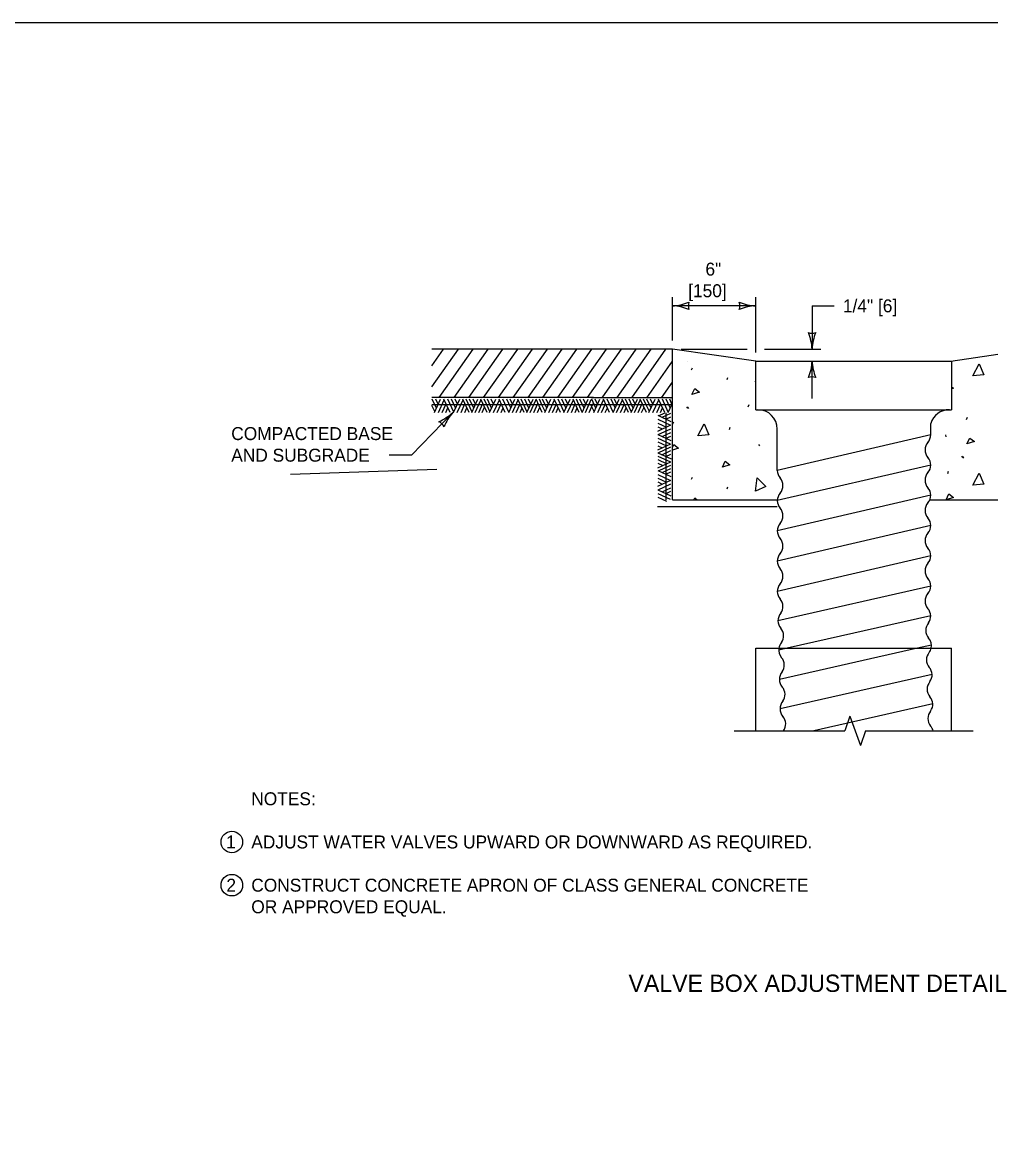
# Model space of a CAD drawing. Extents: x 49991.4 to 50021, y 49987.6 to 50011.4.
# Drawn here: x 50008.62 to 50013.11, y 49993.82 to 49999 of the extents above; entities that cross this region are included whole.
import ezdxf

# ---------------------------------------------------------------- set-up
doc = ezdxf.new("R2010")
doc.units = 0
for name, color, linetype in [('Level 1', 7, 'Continuous'), ('Level 2', 7, 'Continuous'), ('Level 3', 7, 'Continuous'), ('Level 4', 7, 'Continuous'), ('Level 6', 7, 'Continuous')]:
    doc.layers.add(name, color=color, linetype=linetype)

msp = doc.modelspace()

# ---------------------------------------------------------------- linework, layer by layer
at = {"layer": 'Level 1'}
for p, q in [((50011.6341, 49997.4869), (50010.5195, 49997.4869)), ((50010.5195, 49997.4096), (50010.5736, 49997.4869)), ((50010.5195, 49997.3116), (50010.6423, 49997.4869)), ((50010.5534, 49997.2619), (50010.711, 49997.4869)), ((50010.6221, 49997.2619), (50010.7796, 49997.4869)), ((50010.6908, 49997.2619), (50010.8484, 49997.4869)), ((50010.7594, 49997.2619), (50010.917, 49997.4869)), ((50010.8281, 49997.2619), (50010.9857, 49997.4869)), ((50010.8968, 49997.2619), (50011.0543, 49997.4869)), ((50010.9654, 49997.2619), (50011.123, 49997.4869)), ((50011.0341, 49997.2619), (50011.1916, 49997.4869)), ((50011.1028, 49997.2619), (50011.2603, 49997.4869)), ((50011.1714, 49997.2619), (50011.329, 49997.4867)), ((50011.2402, 49997.2619), (50011.3975, 49997.4869)), ((50011.3086, 49997.2617), (50011.4663, 49997.4869)), ((50011.3775, 49997.2619), (50011.5351, 49997.487)), ((50011.4458, 49997.2615), (50011.6035, 49997.487)), ((50011.6341, 49997.4589), (50011.6341, 49997.4869)), ((50012.0195, 49997.4313), (50011.6341, 49997.4869)), ((50012.9239, 49997.4313), (50013.3039, 49997.4869)), ((50011.5146, 49997.2618), (50011.6336, 49997.4316)), ((50011.6341, 49996.7892), (50011.6341, 49997.4589)), ((50011.7013, 49997.4303), (50011.7019, 49997.4312)), ((50012.0195, 49997.4313), (50012.9263, 49997.4313)), ((50012.0195, 49997.2063), (50012.0195, 49997.4313)), ((50012.9263, 49997.4313), (50012.9263, 49997.2063)), ((50011.7219, 49997.3902), (50011.7262, 49997.4)), ((50011.3679, 49997.3458), (50011.3685, 49997.3473)), ((50011.5832, 49997.2616), (50011.6341, 49997.3343)), ((50011.8865, 49997.3458), (50011.8908, 49997.3556)), ((50011.2685, 49997.2619), (50010.5195, 49997.2619)), ((50010.5195, 49997.2304), (50011.2685, 49997.2304)), ((50010.533, 49997.1974), (50010.5195, 49997.2263)), ((50010.5406, 49997.2138), (50010.5214, 49997.2549)), ((50010.5313, 49997.1936), (50010.5597, 49997.2549)), ((50010.5488, 49997.2315), (50010.5382, 49997.2549)), ((50010.5496, 49997.1936), (50010.5768, 49997.2521)), ((50010.5671, 49997.1936), (50010.5856, 49997.2334)), ((50010.6041, 49997.1936), (50010.5755, 49997.2549)), ((50010.5845, 49997.1936), (50010.5942, 49997.2147)), ((50010.6208, 49997.1953), (50010.5932, 49997.2549)), ((50010.6296, 49997.2143), (50010.6109, 49997.2549)), ((50010.6201, 49997.1936), (50010.6485, 49997.2549)), ((50010.6376, 49997.2322), (50010.6273, 49997.2549)), ((50010.637, 49997.1936), (50010.6641, 49997.2519)), ((50010.6546, 49997.1936), (50010.6729, 49997.2334)), ((50010.6915, 49997.1936), (50010.6628, 49997.2549)), ((50010.6725, 49997.1936), (50010.6818, 49997.2141)), ((50010.7054, 49997.1955), (50010.6778, 49997.2549)), ((50010.7136, 49997.2132), (50010.6944, 49997.2549)), ((50010.7045, 49997.1936), (50010.7329, 49997.2551)), ((50010.7222, 49997.2317), (50010.7115, 49997.2549)), ((50010.7197, 49997.1936), (50010.7471, 49997.253)), ((50010.7365, 49997.1936), (50010.7555, 49997.2353)), ((50010.775, 49997.1936), (50010.7466, 49997.2549)), ((50010.7527, 49997.1936), (50010.7637, 49997.2178)), ((50010.775, 49997.2263), (50010.7618, 49997.2549)), ((50010.7885, 49997.1974), (50010.775, 49997.2263)), ((50010.7961, 49997.2138), (50010.7769, 49997.2549)), ((50010.7868, 49997.1936), (50010.8152, 49997.2549)), ((50010.8043, 49997.2315), (50010.7936, 49997.2549)), ((50010.8051, 49997.1936), (50010.8323, 49997.2521)), ((50010.8226, 49997.1936), (50010.8411, 49997.2334)), ((50010.8595, 49997.1936), (50010.831, 49997.2549)), ((50010.8399, 49997.1936), (50010.8496, 49997.2147)), ((50010.8763, 49997.1953), (50010.8487, 49997.2549)), ((50010.8851, 49997.2143), (50010.8664, 49997.2549)), ((50010.8755, 49997.1936), (50010.9039, 49997.2549)), ((50010.8931, 49997.2322), (50010.8828, 49997.2549)), ((50010.8925, 49997.1936), (50010.9196, 49997.2519)), ((50010.91, 49997.1936), (50010.9283, 49997.2334)), ((50010.947, 49997.1936), (50010.9182, 49997.2549)), ((50010.9279, 49997.1936), (50010.9373, 49997.2141)), ((50010.9609, 49997.1955), (50010.9333, 49997.2549)), ((50010.9691, 49997.2132), (50010.9498, 49997.2549)), ((50010.9599, 49997.1936), (50010.9883, 49997.2551)), ((50010.9777, 49997.2317), (50010.967, 49997.2549)), ((50010.9752, 49997.1936), (50011.0026, 49997.253)), ((50010.9919, 49997.1936), (50011.011, 49997.2353)), ((50011.0304, 49997.1936), (50011.002, 49997.2549)), ((50011.0081, 49997.1936), (50011.0192, 49997.2178)), ((50011.0304, 49997.2263), (50011.0173, 49997.2549)), ((50011.0439, 49997.1974), (50011.0304, 49997.2263)), ((50011.0516, 49997.2138), (50011.0323, 49997.2549)), ((50011.0422, 49997.1936), (50011.0706, 49997.2549)), ((50011.0598, 49997.2315), (50011.0491, 49997.2549)), ((50011.0605, 49997.1936), (50011.0878, 49997.2521)), ((50011.078, 49997.1936), (50011.0965, 49997.2334)), ((50011.115, 49997.1936), (50011.0864, 49997.2549)), ((50011.0954, 49997.1936), (50011.1051, 49997.2147)), ((50011.1318, 49997.1953), (50011.1041, 49997.2549)), ((50011.1405, 49997.2143), (50011.1219, 49997.2549)), ((50011.131, 49997.1936), (50011.1594, 49997.2549)), ((50011.1485, 49997.2322), (50011.1382, 49997.2549)), ((50011.148, 49997.1936), (50011.175, 49997.2519)), ((50011.1655, 49997.1936), (50011.1838, 49997.2334)), ((50011.2024, 49997.1936), (50011.1737, 49997.2549)), ((50011.1834, 49997.1936), (50011.1927, 49997.2141)), ((50011.2163, 49997.1955), (50011.1887, 49997.2549)), ((50011.2245, 49997.2132), (50011.2053, 49997.2549)), ((50011.2154, 49997.1936), (50011.2438, 49997.2551)), ((50011.2331, 49997.2317), (50011.2224, 49997.2549)), ((50011.2306, 49997.1936), (50011.2581, 49997.253)), ((50011.2474, 49997.1936), (50011.2664, 49997.2353)), ((50011.2579, 49997.2619), (50011.6341, 49997.2619)), ((50011.2579, 49997.2304), (50011.6341, 49997.2304)), ((50011.2714, 49997.1974), (50011.2579, 49997.2263)), ((50011.279, 49997.2138), (50011.2598, 49997.2549)), ((50011.2697, 49997.1936), (50011.2981, 49997.2549)), ((50011.2872, 49997.2315), (50011.2766, 49997.2549)), ((50011.288, 49997.1936), (50011.3152, 49997.2521)), ((50011.3055, 49997.1936), (50011.324, 49997.2334)), ((50011.3425, 49997.1936), (50011.3139, 49997.2549)), ((50011.3229, 49997.1936), (50011.3326, 49997.2147)), ((50011.3592, 49997.1953), (50011.3316, 49997.2549)), ((50011.368, 49997.2143), (50011.3493, 49997.2549)), ((50011.3585, 49997.1936), (50011.3869, 49997.2549)), ((50011.376, 49997.2322), (50011.3657, 49997.2549)), ((50011.3754, 49997.1936), (50011.4025, 49997.2519)), ((50011.393, 49997.1936), (50011.4112, 49997.2334)), ((50011.4299, 49997.1936), (50011.4011, 49997.2549)), ((50011.4109, 49997.1936), (50011.4202, 49997.2141)), ((50011.4438, 49997.1955), (50011.4162, 49997.2549)), ((50011.452, 49997.2132), (50011.4328, 49997.2549)), ((50011.4429, 49997.1936), (50011.4713, 49997.2551)), ((50011.4606, 49997.2317), (50011.4499, 49997.2549)), ((50011.4581, 49997.1936), (50011.4855, 49997.253)), ((50011.4749, 49997.1936), (50011.4939, 49997.2353)), ((50011.5134, 49997.1936), (50011.485, 49997.2549)), ((50011.4911, 49997.1936), (50011.5021, 49997.2178)), ((50011.5134, 49997.2263), (50011.5002, 49997.2549)), ((50011.5269, 49997.1974), (50011.5134, 49997.2263)), ((50011.5345, 49997.2138), (50011.5153, 49997.2549)), ((50011.5252, 49997.1936), (50011.5535, 49997.2549)), ((50011.5427, 49997.2315), (50011.532, 49997.2549)), ((50011.5434, 49997.1936), (50011.5707, 49997.2521)), ((50011.561, 49997.1936), (50011.5795, 49997.2334)), ((50011.5979, 49997.1936), (50011.5694, 49997.2549)), ((50011.5783, 49997.1936), (50011.588, 49997.2147)), ((50011.6147, 49997.1953), (50011.5871, 49997.2549)), ((50011.6235, 49997.2143), (50011.6048, 49997.2549)), ((50011.6139, 49997.1936), (50011.6334, 49997.2357)), ((50011.6315, 49997.2322), (50011.6212, 49997.2549)), ((50011.6992, 49997.2202), (50011.7035, 49997.2137)), ((50011.7035, 49997.2178), (50011.7078, 49997.2113)), ((50011.985, 49997.2202), (50011.9893, 49997.23)), ((50011.5657, 49997.1802), (50011.6271, 49997.1518)), ((50011.5695, 49997.1785), (50011.5985, 49997.192)), ((50011.5859, 49997.1709), (50011.6271, 49997.1901)), ((50011.6026, 49997.192), (50011.6026, 49996.7892)), ((50011.6036, 49997.1627), (50011.6271, 49997.1733)), ((50012.0195, 49997.2063), (50012.9263, 49997.2063)), ((50012.9955, 49997.1615), (50012.9998, 49997.1712)), ((50011.5657, 49997.1619), (50011.6242, 49997.1347)), ((50011.5657, 49997.1444), (50011.6055, 49997.1259)), ((50011.5657, 49997.1074), (50011.6271, 49997.136)), ((50011.5657, 49997.1271), (50011.5869, 49997.1173)), ((50011.5674, 49997.0907), (50011.6271, 49997.1183)), ((50011.6353, 49997.14), (50011.6396, 49997.1497)), ((50011.8973, 49997.1151), (50011.9016, 49997.1248)), ((50012.1195, 49996.9251), (50012.1195, 49997.1163)), ((50012.8301, 49997.09), (50012.8301, 49997.1423)), ((50011.5657, 49997.0914), (50011.6271, 49997.063)), ((50011.5657, 49997.0745), (50011.624, 49997.0474)), ((50011.5865, 49997.0819), (50011.6271, 49997.1006)), ((50011.6044, 49997.0739), (50011.6271, 49997.0842)), ((50012.8301, 49997.09), (50012.1195, 49996.9251)), ((50012.8988, 49997.0899), (50012.8999, 49997.0802)), ((50011.5657, 49997.0569), (50011.6055, 49997.0387)), ((50011.5657, 49997.02), (50011.6271, 49997.0488)), ((50011.5657, 49997.039), (50011.5863, 49997.0297)), ((50011.5657, 49997.007), (50011.6273, 49996.9787)), ((50011.5676, 49997.0061), (50011.6271, 49997.0337)), ((50011.5854, 49996.9979), (50011.6271, 49997.0171)), ((50012.0326, 49997.0458), (50012.037, 49997.0393)), ((50011.5657, 49996.9918), (50011.6252, 49996.9644)), ((50011.5657, 49996.975), (50011.6075, 49996.956)), ((50011.5657, 49996.9366), (50011.6271, 49996.9649)), ((50011.5657, 49996.9588), (50011.5899, 49996.9478)), ((50011.6038, 49996.9893), (50011.6271, 49997)), ((50012.9727, 49996.9915), (50012.9771, 49996.985)), ((50012.9771, 49996.989), (50012.9814, 49996.9825)), ((50011.5657, 49996.9247), (50011.6271, 49996.8964)), ((50011.5657, 49996.9065), (50011.6242, 49996.8792)), ((50011.5695, 49996.923), (50011.5985, 49996.9366)), ((50011.5859, 49996.9154), (50011.6271, 49996.9346)), ((50011.5985, 49996.9366), (50011.6271, 49996.9497)), ((50011.6036, 49996.9072), (50011.6271, 49996.9179)), ((50012.8301, 49996.95), (50012.1195, 49996.7851)), ((50012.9089, 49996.9113), (50012.9132, 49996.921)), ((50011.5657, 49996.8889), (50011.6055, 49996.8705)), ((50011.5657, 49996.852), (50011.6271, 49996.8805)), ((50011.5657, 49996.8716), (50011.5869, 49996.8619)), ((50011.5674, 49996.8352), (50011.6271, 49996.8628)), ((50011.7219, 49996.8845), (50011.7262, 49996.8942)), ((50011.5657, 49996.836), (50011.6271, 49996.8076)), ((50011.5657, 49996.819), (50011.624, 49996.792)), ((50011.5657, 49996.8015), (50011.6055, 49996.7832)), ((50011.5865, 49996.8264), (50011.6271, 49996.8451)), ((50011.6044, 49996.8184), (50011.6271, 49996.8287)), ((50011.8865, 49996.8401), (50011.8908, 49996.8498)), ((50012.8301, 49996.81), (50012.1195, 49996.6451)), ((50011.5651, 49996.7577), (50012.1195, 49996.7577)), ((50011.6341, 49996.7892), (50012.1195, 49996.7892)), ((50012.1195, 49996.7892), (50012.1197, 49996.7892)), ((50012.8258, 49996.7892), (50013.3039, 49996.7892)), ((50012.8301, 49996.67), (50012.1195, 49996.5051)), ((50012.8301, 49996.53), (50012.1195, 49996.3651)), ((50012.8301, 49996.39), (50012.1227, 49996.2292)), ((50012.83, 49996.2526), (50012.1645, 49996.102)), ((50012.0195, 49996.102), (50012.9263, 49996.102)), ((50012.0195, 49995.7196), (50012.0195, 49996.102)), ((50012.8332, 49996.1167), (50012.7684, 49996.102)), ((50012.9263, 49995.7196), (50012.9263, 49996.102))]:
    msp.add_line(p, q, dxfattribs=at)
msp.add_lwpolyline([(49999.3835, 49998.9992), (50016.7501, 49998.9992), (50016.7501, 49987.7988), (49999.3835, 49987.7988)], close=True, dxfattribs=at)
for points in [[(50013.0247, 49997.3629), (50013.054, 49997.4181), (50013.0767, 49997.3672), (50013.0258, 49997.3629)], [(50012.0182, 49997.3346), (50012.0195, 49997.3439)], [(50012.0195, 49997.3351), (50012.0192, 49997.335)], [(50011.7241, 49997.2765), (50011.7371, 49997.3036), (50011.7587, 49997.2874), (50011.7241, 49997.2765)], [(50012.9263, 49997.3127), (50012.9359, 49997.3055), (50012.9263, 49997.3025)], [(50011.7512, 49997.0859), (50011.7804, 49997.1411), (50011.8031, 49997.0902), (50011.7522, 49997.0859)], [(50011.7512, 49997.0859), (50011.7804, 49997.1411), (50011.8031, 49997.0902), (50011.7522, 49997.0859)], [(50012.9977, 49997.0478), (50013.0107, 49997.0749), (50013.0323, 49997.0586), (50012.9977, 49997.0478)], [(50011.6341, 49997.0309), (50011.6407, 49997.0447), (50011.6623, 49997.0285), (50011.6341, 49997.0196)], [(50011.865, 49996.9403), (50011.878, 49996.9673), (50011.8997, 49996.9511), (50011.865, 49996.9403)], [(50013.0247, 49996.8571), (50013.054, 49996.9123), (50013.0767, 49996.8615), (50013.0258, 49996.8571)], [(50012.0182, 49996.8289), (50012.0268, 49996.8908), (50012.0656, 49996.8507), (50012.0192, 49996.8293)], [(50012.9014, 49996.7892), (50012.9143, 49996.816), (50012.9359, 49996.7997), (50012.9021, 49996.7892)], [(50011.7329, 49996.7892), (50011.7371, 49996.7979), (50011.7487, 49996.7892)]]:
    msp.add_lwpolyline(points, dxfattribs=at)
for centre, radius, start, end in [((50012.0295, 49997.1163), 0.09, 0, 90), ((50012.9163, 49997.1163), 0.09, 90, 163.2395), ((50012.7768, 49997.09), 0.0533, 318.9597, 0), ((50012.8572, 49997.02), 0.0533, 138.9597, 221.0403), ((50012.7768, 49996.95), 0.0533, 318.9597, 41.0403), ((50012.1728, 49996.9251), 0.0533, 180, 221.0403), ((50012.8572, 49996.88), 0.0533, 138.9597, 221.0403), ((50012.0924, 49996.8551), 0.0533, 318.9597, 41.0403), ((50012.1728, 49996.7851), 0.0533, 138.9597, 221.0403), ((50012.7768, 49996.81), 0.0533, 318.9597, 41.0403), ((50012.0924, 49996.7151), 0.0533, 318.9597, 41.0403), ((50012.8572, 49996.74), 0.0533, 138.9597, 221.0403), ((50012.7768, 49996.67), 0.0533, 318.9597, 41.0403), ((50012.1728, 49996.6451), 0.0533, 138.9597, 221.0403), ((50012.0924, 49996.5751), 0.0533, 318.9597, 41.0403), ((50012.8572, 49996.6), 0.0533, 138.9597, 221.0403), ((50012.7768, 49996.53), 0.0533, 318.9597, 41.0403), ((50012.1728, 49996.5051), 0.0533, 138.9597, 221.0403), ((50012.8572, 49996.46), 0.0533, 138.9597, 221.0403), ((50012.0924, 49996.4351), 0.0533, 318.9597, 41.0403), ((50012.1728, 49996.3651), 0.0533, 138.9597, 221.0403), ((50012.7768, 49996.39), 0.0533, 318.9597, 41.0403), ((50012.8572, 49996.32), 0.0533, 138.9597, 221.0403), ((50012.0924, 49996.2951), 0.0533, 324.5794, 41.0403), ((50012.7768, 49996.25), 0.0533, 324.5794, 41.0403), ((50012.176, 49996.2292), 0.0533, 138.9597, 221.0403), ((50012.0956, 49996.1592), 0.0533, 324.5794, 41.0403), ((50012.8604, 49996.1841), 0.0533, 138.9597, 221.0403), ((50012.1792, 49996.0933), 0.0533, 138.9597, 170.6068), ((50012.78, 49996.1141), 0.0533, 346.8799, 41.0403)]:
    msp.add_arc(centre, radius, start, end, dxfattribs=at)
at = {"layer": 'Level 2'}
for centre in [(50009.593, 49995.2051), (50009.593, 49995.0051)]:
    msp.add_circle(centre, 0.05, dxfattribs=at)
at = {"layer": 'Level 3'}
for p, q in [((50011.6341, 49997.5269), (50011.6341, 49997.7269)), ((50012.0195, 49997.6869), (50011.6341, 49997.6869)), ((50011.715, 49997.6869), (50011.635, 49997.6869)), ((50012.0195, 49997.4713), (50012.0195, 49997.7269)), ((50012.2807, 49997.6869), (50012.3834, 49997.6869)), ((50012.2807, 49997.6869), (50012.2807, 49997.4869)), ((50011.6341, 49997.4869), (50011.6341, 49997.4869)), ((50011.6741, 49997.4869), (50011.9795, 49997.4869)), ((50012.0595, 49997.4869), (50012.3207, 49997.4869)), ((50012.2807, 49997.2579), (50012.2807, 49997.4313)), ((50010.6167, 49997.1936), (50010.4248, 49996.9956)), ((50010.4248, 49996.9956), (50010.3221, 49996.9956)), ((50010.4248, 49996.9956), (50010.3221, 49996.9956))]:
    msp.add_line(p, q, dxfattribs=at)
for centre, radius, start, end in [((50011.6226, 49997.9196), 0.233, 272.8273, 292.0772), ((50011.6249, 49997.4648), 0.2223, 67.456, 87.6395), ((50011.7623, 49997.6869), 0.0548, 162.1388, 197.8612), ((50012.0286, 49997.9091), 0.2223, 247.456, 267.6395), ((50011.8913, 49997.6869), 0.0548, 342.1388, 17.8612), ((50012.031, 49997.4542), 0.233, 92.8273, 112.0772), ((50012.2807, 49997.6152), 0.0548, 252.1388, 287.8612), ((50012.048, 49997.4754), 0.233, 2.8273, 22.0772), ((50012.5028, 49997.4778), 0.2223, 157.456, 177.6395), ((50012.0586, 49997.4405), 0.2223, 337.456, 357.6395), ((50012.5134, 49997.4428), 0.233, 182.8273, 202.0772), ((50012.2807, 49997.3031), 0.0548, 72.1388, 107.8612), ((50010.4577, 49997.3639), 0.233, 293.8096, 313.0595), ((50010.7826, 49997.0456), 0.2223, 138.2473, 158.4308), ((50010.5275, 49997.1016), 0.0548, 28.0256, 63.748)]:
    msp.add_arc(centre, radius, start, end, dxfattribs=at)
at = {"layer": 'Level 4'}
for p, q in [((50009.8646, 49996.9075), (50010.543, 49996.9305)), ((50012.1645, 49996.102), (50012.1259, 49996.0933)), ((50012.7682, 49996.102), (50012.1291, 49995.9574)), ((50012.8364, 49995.9808), (50012.1323, 49995.8215)), ((50012.8396, 49995.8449), (50012.2884, 49995.7196))]:
    msp.add_line(p, q, dxfattribs=at)
for centre, start, end in [((50012.1792, 49996.0933), 170.6068, 221.0403), ((50012.8636, 49996.0482), 138.9597, 221.0403), ((50012.78, 49996.1141), 324.5794, 346.8799), ((50012.0988, 49996.0233), 324.5794, 41.0403), ((50012.1824, 49995.9574), 138.9597, 221.0403), ((50012.7832, 49995.9782), 324.5794, 41.0403), ((50012.102, 49995.8874), 324.5794, 41.0403), ((50012.8668, 49995.9123), 138.9597, 221.0403), ((50012.7864, 49995.8423), 324.5794, 41.0403), ((50012.1856, 49995.8215), 138.9597, 221.0403), ((50012.1052, 49995.7515), 323.2421, 41.0403), ((50012.87, 49995.7764), 138.9597, 221.0403), ((50012.7896, 49995.7064), 14.3372, 41.0403)]:
    msp.add_arc(centre, 0.0533, start, end, dxfattribs=at)
at = {"layer": 'Level 6'}
for p, q in [((50012.4557, 49995.7882), (50012.4315, 49995.7196)), ((50012.4557, 49995.7882), (50012.4801, 49995.7196)), ((50011.9195, 49995.7196), (50012.4315, 49995.7196)), ((50012.4801, 49995.7196), (50012.5043, 49995.651)), ((50012.5287, 49995.7196), (50012.5043, 49995.651)), ((50012.5287, 49995.7196), (50013.0263, 49995.7196))]:
    msp.add_line(p, q, dxfattribs=at)

# ---------------------------------------------------------------- texts
at = {"layer": 'Level 2'}
for s, height, p in [('6"', 0.06, (50011.7866, 49997.8269)), ('[150]', 0.06, (50011.7067, 49997.7269)), ('1/4" [6]', 0.06, (50012.4234, 49997.6569)), ('COMPACTED BASE', 0.06, (50009.5902, 49997.0656)), ('AND SUBGRADE', 0.06, (50009.5902, 49996.9656)), ('NOTES:', 0.06, (50009.683, 49995.3751)), ('1', 0.06, (50009.5663, 49995.1752)), ('ADJUST WATER VALVES UPWARD OR DOWNWARD AS REQUIRED.', 0.06, (50009.683, 49995.1751)), ('2', 0.06, (50009.5678, 49994.9751)), ('CONSTRUCT CONCRETE APRON OF CLASS GENERAL CONCRETE ', 0.06, (50009.683, 49994.9751)), ('OR APPROVED EQUAL.', 0.06, (50009.683, 49994.8751)), ('VALVE BOX ADJUSTMENT DETAIL', 0.08, (50011.4303, 49994.5111))]:
    msp.add_text(s, height=height, dxfattribs=at).set_placement(p)

doc.saveas('drawing.dxf')
